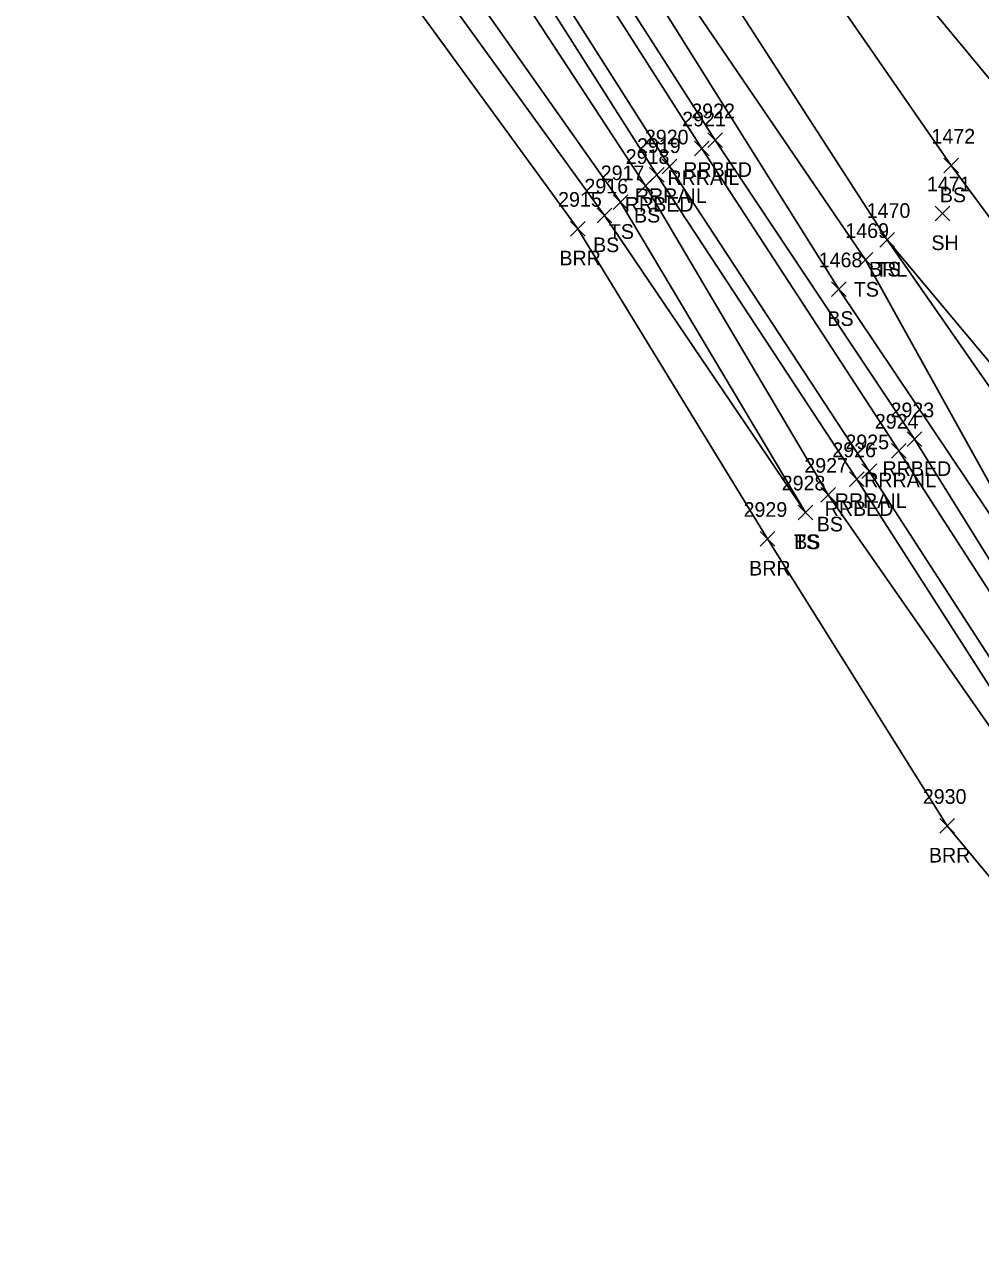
# Model space of a CAD drawing. Extents: x 1505656 to 1508446, y 700805 to 703031.
# Drawn here: x 1506226.3 to 1506356.7, y 701922.6 to 702088 of the extents above; entities that cross this region are included whole.
import ezdxf

# ---------------------------------------------------------------- set-up
doc = ezdxf.new("R2010")
doc.units = 0
for name, color, linetype in [('L_A', 7, 'Continuous'), ('L_I', 7, 'Continuous'), ('L_TIC', 7, 'Continuous'), ('LABL', 7, 'Continuous'), ('LELB', 7, 'Continuous'), ('R_A', 7, 'Continuous'), ('R_I', 7, 'Continuous'), ('R_TIC', 7, 'Continuous'), ('RR', 7, 'Continuous'), ('RRB', 7, 'Continuous')]:
    doc.layers.add(name, color=color, linetype=linetype)

msp = doc.modelspace()

# ---------------------------------------------------------------- linework, layer by layer
at = {"layer": 'L_TIC'}
for points in [[(1506351.66, 702067.74), (1506353.66, 702069.74)], [(1506353.66, 702067.74), (1506351.66, 702069.74)], [(1506309.98, 702064.97), (1506311.98, 702066.97)], [(1506311.98, 702064.97), (1506309.98, 702066.97)], [(1506306.58, 702062.75), (1506308.58, 702064.75)], [(1506308.58, 702062.75), (1506306.58, 702064.75)], [(1506304.4, 702060.94), (1506306.4, 702062.94)], [(1506306.4, 702060.94), (1506304.4, 702062.94)], [(1506350.46, 702061.22), (1506352.46, 702063.22)], [(1506352.46, 702061.22), (1506350.46, 702063.22)], [(1506300.77, 702059.13), (1506302.77, 702061.13)], [(1506302.77, 702059.13), (1506300.77, 702061.13)], [(1506342.91, 702057.61), (1506344.91, 702059.61)], [(1506344.91, 702057.61), (1506342.91, 702059.61)], [(1506342.91, 702057.61), (1506344.91, 702059.61)], [(1506344.91, 702057.61), (1506342.91, 702059.61)], [(1506339.97, 702054.87), (1506341.97, 702056.87)], [(1506341.97, 702054.87), (1506339.97, 702056.87)], [(1506336.33, 702050.88), (1506338.33, 702052.88)], [(1506338.33, 702050.88), (1506336.33, 702052.88)], [(1506334.89, 702022.86), (1506336.89, 702024.86)], [(1506336.89, 702022.86), (1506334.89, 702024.86)], [(1506331.81, 702020.45), (1506333.81, 702022.45)], [(1506333.81, 702020.45), (1506331.81, 702022.45)], [(1506331.81, 702020.45), (1506333.81, 702022.45)], [(1506333.81, 702020.45), (1506331.81, 702022.45)], [(1506326.62, 702016.85), (1506328.62, 702018.85)], [(1506328.62, 702016.85), (1506326.62, 702018.85)], [(1506351.12, 701977.72), (1506353.12, 701979.72)], [(1506353.12, 701977.72), (1506351.12, 701979.72)]]:
    msp.add_lwpolyline(points, dxfattribs=at)
at = {"layer": 'LABL'}
for points in [[(1506097.89, 702451.48), (1506093.59, 702448.31), (1506114.07, 702419.3), (1506137.72, 702376.05), (1506165.52, 702335.14), (1506176.55, 702314.38), (1506188.56, 702296.46), (1506197.64, 702285.72), (1506210.24, 702262.45), (1506236.39, 702222.1), (1506262.97, 702180.71), (1506287.88, 702142.77), (1506318.3, 702098.36), (1506343.91, 702058.61), (1506370.15, 702020.94), (1506392.92, 701982.02), (1506408.75, 701957.63), (1506404.6, 701955.65), (1506415.57, 701943.72), (1506429.75, 701925.56), (1506437.71, 701917.37), (1506453.7, 701897.97), (1506473.58, 701870.51), (1506501.09, 701827)], [(1506097.89, 702451.48), (1506119.33, 702422.59), (1506147.14, 702381.23), (1506170.74, 702339.27), (1506181.05, 702317.33), (1506195.31, 702300.85), (1506204.63, 702289.22), (1506217.94, 702268), (1506249.76, 702230.45), (1506275.61, 702192.02), (1506301.13, 702151.48), (1506333.13, 702110.45), (1506362.68, 702074.77), (1506393.24, 702036.24), (1506419.01, 702002.4), (1506440.79, 701985.8), (1506459.2, 701943.61), (1506474.51, 701912.21), (1506491.96, 701880.66), (1506505.67, 701860.23), (1506521.4, 701845.88), (1506529.18, 701832.12), (1506516.38, 701828.81), (1506501.09, 701827)], [(1506270.22, 702103.44), (1506301.77, 702060.13), (1506327.62, 702017.85), (1506352.12, 701978.72), (1506381.47, 701943.35), (1506404.22, 701904.97), (1506405.42, 701902.64), (1506427.03, 701865.87), (1506439.87, 701843.69), (1506458.47, 701818.08), (1506448.56, 701811.95), (1506441.61, 701824.07), (1506420.95, 701839.99), (1506407.54, 701857.98)]]:
    msp.add_lwpolyline(points, dxfattribs=at)
at = {"layer": 'LELB'}
for points in [[(1505941.54, 702671.13), (1505960.91, 702641.21), (1505983.85, 702606.41), (1506009.66, 702565.58), (1506036.17, 702525.55), (1506062.35, 702483.61), (1506087.3, 702443.66), (1506107.03, 702410.49), (1506132.1, 702372.93), (1506158.96, 702331.11), (1506171.73, 702310.51), (1506183.6, 702292.09), (1506190.68, 702281.13), (1506204.66, 702258.81), (1506230.37, 702218.88), (1506257.75, 702177.44), (1506282.28, 702138.54), (1506311.28, 702093.48), (1506337.33, 702051.88), (1506360.11, 702017.94), (1506385.57, 701975.18)], [(1506130.25, 702337.83), (1506153.31, 702301.79), (1506180.15, 702262.6), (1506204.32, 702223), (1506229.62, 702183.9), (1506252.28, 702148.49), (1506276.64, 702107.67), (1506307.58, 702063.75), (1506332.81, 702021.45)], [(1506188.56, 702296.46), (1506192.93, 702283.04), (1506207.33, 702260.5), (1506233.6, 702220.79), (1506259.91, 702179.3), (1506284.93, 702140.8), (1506313.83, 702095.76), (1506340.97, 702055.87), (1506361.09, 702019.6), (1506387.67, 701976.73), (1506404.6, 701955.65)], [(1506217.94, 702268), (1506241.75, 702226.26), (1506266.61, 702184.29), (1506291.5, 702144.91), (1506326.97, 702105.86), (1506352.66, 702068.74), (1506380.93, 702030.46), (1506410.26, 701994.34), (1506417.88, 701971.26), (1506422.76, 701954.38), (1506429.75, 701925.56), (1506435.03, 701911.2)], [(1506208.26, 702225.34), (1506233.07, 702186.13), (1506256.11, 702150.88), (1506281.7, 702110.75), (1506310.98, 702065.97), (1506335.89, 702023.86), (1506362.15, 701986.17), (1506387.44, 701946.03), (1506412.53, 701907.73), (1506436.18, 701872.35), (1506448.78, 701849.5), (1506468, 701820.56), (1506480.93, 701799.85), (1506497.59, 701775.16), (1506503.35, 701767.24), (1506509.31, 701758.89), (1506523.55, 701737.24), (1506530.48, 701722.02), (1506538.47, 701708.02), (1506540.17, 701706.71), (1506553.68, 701688.5), (1506562.31, 701674.17), (1506570.51, 701664.87), (1506574.8, 701654.41)], [(1506199.37, 702218.13), (1506226.59, 702180.83), (1506249.6, 702145.67), (1506273.74, 702105.75), (1506305.4, 702061.94), (1506332.81, 702021.45)], [(1506343.91, 702058.61), (1506372.57, 702024.35), (1506398.42, 701985.47), (1506414.88, 701960.49), (1506415.57, 701943.72)]]:
    msp.add_lwpolyline(points, dxfattribs=at)
at = {"layer": 'R_TIC'}
for points in [[(1506319.48, 702071.19), (1506321.48, 702073.19)], [(1506321.48, 702071.19), (1506319.48, 702073.19)], [(1506317.67, 702070.08), (1506319.67, 702072.08)], [(1506319.67, 702070.08), (1506317.67, 702072.08)], [(1506311.53, 702066.46), (1506313.53, 702068.46)], [(1506313.53, 702066.46), (1506311.53, 702068.46)], [(1506313.24, 702067.63), (1506315.24, 702069.63)], [(1506315.24, 702067.63), (1506313.24, 702069.63)], [(1506346.64, 702030.42), (1506348.64, 702032.42)], [(1506348.64, 702030.42), (1506346.64, 702032.42)], [(1506344.5, 702028.87), (1506346.5, 702030.87)], [(1506346.5, 702028.87), (1506344.5, 702030.87)], [(1506338.77, 702024.98), (1506340.77, 702026.98)], [(1506340.77, 702024.98), (1506338.77, 702026.98)], [(1506340.49, 702026.06), (1506342.49, 702028.06)], [(1506342.49, 702026.06), (1506340.49, 702028.06)]]:
    msp.add_lwpolyline(points, dxfattribs=at)
at = {"layer": 'RR'}
for points in [[(1506216.22, 702230.61), (1506241.14, 702191.91), (1506264.22, 702156.05), (1506289.37, 702116.98), (1506318.67, 702071.08), (1506345.5, 702029.87), (1506369.8, 701992.12), (1506395.94, 701951.53), (1506421.29, 701912.09)], [(1506212.18, 702227.87), (1506237.14, 702189.06), (1506259.99, 702153.6), (1506285.64, 702113.68), (1506314.24, 702068.63), (1506341.49, 702027.06), (1506364.79, 701991.04), (1506391.76, 701949.05), (1506416.43, 701910.5)]]:
    msp.add_lwpolyline(points, dxfattribs=at)
at = {"layer": 'RRB'}
for points in [[(1506218.21, 702231.87), (1506243.42, 702192.99), (1506265.65, 702156.97), (1506291.15, 702118.11), (1506320.48, 702072.19), (1506347.64, 702031.42), (1506371.5, 701993.07), (1506397.74, 701952.64), (1506422.13, 701913.03), (1506446.3, 701877.37), (1506459.9, 701856.6), (1506479.2, 701826.27), (1506491.07, 701808.2), (1506507.81, 701783.16), (1506518.9, 701765.85), (1506532.83, 701744.11), (1506551.14, 701715.12), (1506563.36, 701695.79), (1506572.4, 701681.69), (1506577.69, 701674.71), (1506587.05, 701661.96)], [(1506210.03, 702226.7), (1506235.37, 702188.01), (1506257.82, 702152.36), (1506283.92, 702112.55), (1506312.53, 702067.46), (1506339.77, 702025.98), (1506362.71, 701990.18), (1506390.11, 701948.06), (1506413.74, 701910.02), (1506437.48, 701874.06), (1506451.69, 701851.34), (1506470.61, 701821.88), (1506483.37, 701801.54), (1506500.23, 701776.89), (1506510.87, 701760), (1506525.08, 701738.28), (1506533.53, 701723.99), (1506542.09, 701710.78), (1506543.9, 701708.68), (1506555.78, 701690.22), (1506571.64, 701665.34), (1506576.24, 701655.23)]]:
    msp.add_lwpolyline(points, dxfattribs=at)

# ---------------------------------------------------------------- texts
at = {"layer": 'L_A'}
for s, p in [('BS', (1506351.1, 702063.74)), ('BS', (1506309.42, 702060.97)), ('TS', (1506305.99, 702058.75)), ('BS', (1506303.84, 702056.94)), ('SH', (1506349.95, 702057.22)), ('BRR', (1506299.25, 702055.13)), ('BRL', (1506341.45, 702053.61)), ('TS', (1506342.32, 702053.61)), ('TS', (1506339.38, 702050.87)), ('BS', (1506335.77, 702046.88)), ('BS', (1506334.33, 702018.86)), ('TS', (1506331.22, 702016.45)), ('BS', (1506331.25, 702016.45)), ('BRR', (1506325.11, 702012.85)), ('BRR', (1506349.61, 701973.72))]:
    msp.add_text(s, height=2, dxfattribs=at).set_placement(p)
at = {"layer": 'L_I'}
for s, p in [('1472', (1506349.96, 702071.74)), ('2918', (1506308.29, 702068.97)), ('2917', (1506304.88, 702066.75)), ('2916', (1506302.66, 702064.94)), ('1471', (1506349.34, 702065.22)), ('2915', (1506299.07, 702063.13)), ('1470', (1506341.13, 702061.61)), ('1470', (1506341.13, 702061.61)), ('1469', (1506338.22, 702058.87)), ('1468', (1506334.59, 702054.88)), ('2927', (1506332.63, 702026.86)), ('2928', (1506329.55, 702024.45)), ('2928', (1506329.55, 702024.45)), ('2929', (1506324.35, 702020.85)), ('2930', (1506348.78, 701981.72))]:
    msp.add_text(s, height=2, dxfattribs=at).set_placement(p)
at = {"layer": 'R_A'}
for s, p in [('RRBED', (1506316.13, 702067.19)), ('RRRAIL', (1506313.97, 702066.08)), ('RRRAIL', (1506309.53, 702063.63)), ('RRBED', (1506308.17, 702062.46)), ('RRRAIL', (1506340.79, 702024.87)), ('RRBED', (1506343.29, 702026.42)), ('RRRAIL', (1506336.78, 702022.06)), ('RRBED', (1506335.41, 702020.98))]:
    msp.add_text(s, height=2, dxfattribs=at).set_placement(p)
at = {"layer": 'R_I'}
for s, p in [('2922', (1506317.22, 702075.19)), ('2921', (1506315.98, 702074.08)), ('2920', (1506310.9, 702071.63)), ('2919', (1506309.83, 702070.46)), ('2923', (1506344.38, 702034.42)), ('2924', (1506342.24, 702032.87)), ('2925', (1506338.23, 702030.06)), ('2926', (1506336.45, 702028.98))]:
    msp.add_text(s, height=2, dxfattribs=at).set_placement(p)

doc.saveas('drawing.dxf')
